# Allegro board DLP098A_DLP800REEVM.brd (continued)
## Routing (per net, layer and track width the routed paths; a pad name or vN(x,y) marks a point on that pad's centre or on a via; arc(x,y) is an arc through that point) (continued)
M_DDA14_N: length 124.5
  TOP w0.108: U8.B23 v1(46.2,42.39)
  03_SIG1 w0.108: v1(96.18,76.98) 95.67,77.49 95.67,78.79 95.28,79.18 87,79.18 86.53,78.71 86.53,66.09 84.75,64.31 80.52,64.31 79.94,63.73 79.94,56.14 76.47,52.68 60.59,52.68 59.9,53.37 58.27,53.37 57.99,53.65 57.99,53.96 58.35,54.32 60.51,54.32 61.46,53.37 74.97,53.37 75.32,53.73 75.32,54.24 74.98,54.58 61.94,54.58 60.16,56.37 58.1,56.37 56.15,54.42 56.15,49.62 55.61,49.08 55.61,46.45 51.05,41.88 46.31,41.88 46.2,41.99 v1(46.2,42.39)
  BOTTOM w0.108: J500.G34 v1(96.18,76.98)
M_DDA14_P: length 124.5
  TOP w0.108: U8.C23 v1(46.2,41.12)
  03_SIG1 w0.108: v1(46.2,41.12) 46.2,41.52 46.31,41.63 51.15,41.63 55.86,46.34 55.86,48.98 56.4,49.52 56.4,54.32 58.2,56.11 60.05,56.11 61.84,54.33 74.88,54.33 75.07,54.14 75.07,53.83 74.86,53.62 61.57,53.62 60.61,54.58 58.25,54.58 57.73,54.06 57.73,53.54 58.16,53.11 59.79,53.11 60.48,52.42 76.58,52.42 80.19,56.04 80.19,63.62 80.62,64.06 84.85,64.06 86.78,65.99 86.78,78.61 87.1,78.93 95.17,78.93 95.41,78.68 95.41,76.97 95.28,76.84 95.06,76.84 v1(94.91,76.98)
  BOTTOM w0.108: J500.G33 v1(94.91,76.98)
M_DDA15_N: length 124.5
  TOP w0.108: U8.K24 v1(47.47,32.23)
  03_SIG1 w0.108: v1(101.26,75.71) 101.2,75.71 100.83,76.08 100.44,76.47 99.53,76.47 99.23,76.17 99.23,73.87 101.4,71.71 104.02,71.71 105.2,70.53 105.2,68.79 106.77,67.22 112.11,67.22 115.08,64.25 115.08,58.08 112.02,55.02 87.74,55.02 82.81,50.08 82.81,46.6 70.52,34.31 60.25,34.31 58.84,35.72 58.84,37.99 58.46,38.37 57.86,38.37 57.41,37.92 57.41,31.96 55.71,30.26 48.54,30.26 48.24,30.56 48.24,31.47 47.98,31.72 47.58,31.72 47.47,31.83 v1(47.47,32.23)
  BOTTOM w0.108: J500.H38 v1(101.26,75.71)
M_DDA15_P: length 124.5
  TOP w0.108: U8.L24 v1(47.47,30.96)
  03_SIG1 w0.108: v1(99.99,75.71) 100.14,75.56 100.36,75.56 100.53,75.73 100.53,76.02 100.33,76.22 99.64,76.22 99.49,76.07 99.49,73.98 101.5,71.97 104.13,71.97 105.46,70.64 105.46,68.89 106.88,67.48 112.22,67.48 115.34,64.35 115.34,57.98 112.13,54.76 87.85,54.76 83.06,49.98 83.06,46.5 70.62,34.05 60.15,34.05 58.59,35.61 58.59,37.89 58.36,38.12 57.97,38.12 57.67,37.82 57.67,31.85 55.82,30 48.43,30 47.98,30.45 47.98,31.36 47.87,31.47 47.58,31.47 47.47,31.36 v1(47.47,30.96)
  BOTTOM w0.108: J500.H37 v1(99.99,75.71)
M_DDB00_N: length 124.5
  TOP w0.108: U8.Z18 v1(39.85,15.72)
  08_SIG3 w0.108: v1(39.85,15.72) 39.85,15.45 40,15.31 40.25,15.31 40.36,15.43 40.36,19.92 41.43,21 44.85,21 45.42,21.56 47.81,21.56 47.98,21.73 47.98,22.53 48.29,22.83 50.41,22.83 53.34,25.76 53.34,43.04 62.5,52.2 82.33,52.2 82.96,52.83 82.96,54.2 82.2,54.96 74.98,54.96 72.29,57.64 69.53,57.64 69.03,58.14 69.03,61.21 69.57,61.74 84.78,61.74 86.25,63.21 86.25,72.65 86.52,72.91 86.52,73.49 86.35,73.67 85.69,73.67 85.53,73.51 85.53,73.18 85.64,73.07 85.92,73.07 v1(86.02,73.17)
  BOTTOM w0.108: J500.K26 v1(86.02,73.17)
M_DDB00_P: length 124.5
  TOP w0.108: U8.Z19 v1(41.12,15.72)
  08_SIG3 w0.108: v1(41.12,15.72) 40.72,15.72 40.62,15.83 40.62,19.82 41.54,20.74 44.96,20.74 45.52,21.31 47.92,21.31 48.24,21.63 48.24,22.42 48.39,22.58 50.52,22.58 53.59,25.66 53.59,42.94 62.6,51.95 82.44,51.95 83.22,52.73 83.22,54.3 82.31,55.21 75.08,55.21 72.4,57.89 69.64,57.89 69.29,58.25 69.29,61.1 69.67,61.49 84.89,61.49 86.51,63.11 86.51,72.54 86.78,72.81 86.78,73.6 86.45,73.92 85.59,73.92 85.28,73.61 85.28,73.28 85.17,73.17 v1(84.75,73.17)
  BOTTOM w0.108: J500.K25 v1(84.75,73.17)
M_DDB01_N: length 124.5
  TOP w0.108: U8.T24 v1(47.47,23.34)
  08_SIG3 w0.108: v1(47.47,23.34) 47.47,22.94 47.37,22.83 47.21,22.83 46.97,23.08 46.97,24.88 47.21,25.12 50.54,25.12 52.82,27.39 52.82,43.48 62.45,53.11 81.98,53.11 82.24,53.38 82.24,54.01 81.96,54.3 66.39,54.3 66.23,54.46 66.23,54.79 66.4,54.96 71.57,54.96 72.07,55.46 72.07,56.47 71.63,56.9 68.46,56.9 68.01,57.35 68.01,61.94 68.49,62.42 84.32,62.42 85.34,63.44 85.34,71.53 84.24,72.63 84.24,74.04 84.12,74.16 84.12,74.32 84.24,74.44 v1(84.75,74.44)
  BOTTOM w0.108: J500.J25 v1(84.75,74.44)
M_DDB01_P: length 124.5
  TOP w0.108: U8.U24 v1(47.47,22.07)
  08_SIG3 w0.108: v1(47.47,22.07) 47.47,22.47 47.37,22.58 47.11,22.58 46.72,22.97 46.72,24.99 47.1,25.37 50.44,25.37 52.57,27.5 52.57,43.58 62.35,53.37 81.87,53.37 81.99,53.48 81.99,53.91 81.85,54.04 66.28,54.04 65.98,54.35 65.98,54.9 66.29,55.21 71.46,55.21 71.81,55.57 71.81,56.36 71.53,56.65 68.35,56.65 67.75,57.25 67.75,62.05 68.38,62.68 84.21,62.68 85.08,63.55 85.08,71.43 83.99,72.52 83.99,73.93 v1(83.48,74.44)
  BOTTOM w0.108: J500.J24 v1(83.48,74.44)
M_DDB02_N: length 124.5
  TOP w0.108: U8.N23 v1(46.2,27.15)
  08_SIG3 w0.108: v1(82.21,78.25) 81.91,78.25 81.8,78.36 81.8,78.84 81.43,79.22 77.24,79.22 76.37,78.35 76.37,73 77.31,72.06 82.38,72.06 83.16,71.29 83.16,64.27 82.51,63.62 68.23,63.62 67.95,63.9 67.95,64.3 68.22,64.57 81.11,64.57 81.41,64.86 81.41,65.5 81.14,65.76 67.65,65.76 66.63,64.75 66.63,56.86 66.01,56.24 63.98,56.24 51.79,44.04 51.79,29.39 50.31,27.91 46.98,27.91 46.7,27.63 46.7,26.88 46.47,26.64 46.31,26.64 46.2,26.75 v1(46.2,27.15)
  BOTTOM w0.108: J500.F23 v1(82.21,78.25)
M_DDB02_P: length 124.5
  TOP w0.108: U8.P23 v1(46.2,25.88)
  08_SIG3 w0.108: v1(46.2,25.88) 46.2,26.28 46.31,26.39 46.57,26.39 46.95,26.77 46.95,27.53 47.08,27.66 50.42,27.66 52.04,29.28 52.04,43.94 64.09,55.98 66.11,55.98 66.89,56.76 66.89,64.64 67.76,65.51 81.04,65.51 81.15,65.39 81.15,64.97 81.01,64.82 68.12,64.82 67.7,64.4 67.7,63.79 68.12,63.37 82.61,63.37 83.41,64.16 83.41,71.39 82.49,72.31 77.42,72.31 76.62,73.1 76.62,78.25 77.35,78.97 81.32,78.97 81.55,78.74 81.55,78.23 81.41,78.09 81.11,78.09 v1(80.94,78.25)
  BOTTOM w0.108: J500.F22 v1(80.94,78.25)
M_DDB03_N: length 124.4
  TOP w0.108: U8.Y18 v1(39.85,16.99)
  10_SIG4 w0.108: v1(39.85,16.99) 40.25,16.99 40.36,17.1 40.36,20.01 41.13,20.78 43.64,20.78 44.73,21.87 44.73,30.89 45.56,31.72 50.23,31.72 50.89,32.38 50.89,45.47 51.32,45.9 52.05,45.9 52.49,45.46 52.49,35.56 52.78,35.27 53.76,35.27 54.41,35.92 55.86,35.92 56.22,36.28 56.22,45.25 61.1,50.13 71.58,50.13 76.82,55.36 81.8,55.36 83.06,56.62 83.06,72.11 82.71,72.45 82.71,81.14 82.55,81.3 80.54,81.3 80.33,81.1 80.33,80.62 80.45,80.5 80.76,80.5 80.94,80.68 v1(80.94,80.79)
  BOTTOM w0.108: J500.E22 v1(80.94,80.79)
M_DDB03_P: length 124.4
  TOP w0.108: U8.Y19 v1(41.12,16.99)
  10_SIG4 w0.108: v1(41.12,16.99) 40.72,16.99 40.62,17.1 40.62,19.91 41.24,20.53 43.75,20.53 44.99,21.77 44.99,30.79 45.67,31.47 50.33,31.47 51.14,32.28 51.14,45.36 51.43,45.65 51.95,45.65 52.24,45.36 52.24,35.45 52.68,35.02 53.87,35.02 54.51,35.66 55.97,35.66 56.48,36.17 56.48,45.15 61.2,49.87 71.69,49.87 76.92,55.11 81.91,55.11 83.31,56.51 83.31,72.21 82.97,72.56 82.97,81.24 82.66,81.55 80.43,81.55 v1(79.67,80.79)
  BOTTOM w0.108: J500.E21 v1(79.67,80.79)
M_DDB04_N: length 124.5
  TOP w0.108: U8.AA19 v1(41.12,14.45)
  08_SIG3 w0.108: v1(86.02,78.25) 86.02,78.03 85.89,77.89 85.54,77.89 85.4,78.03 85.4,78.81 85.57,78.98 88.7,78.98 89.06,78.62 89.06,72.22 88.46,71.62 88.46,61.55 86.64,59.74 78.21,59.74 77.44,58.96 77.44,57.61 78.24,56.8 84.31,56.8 85.57,55.54 85.57,51.39 84.6,50.42 63.23,50.42 55.12,42.31 55.12,24.84 50.58,20.29 41.98,20.29 41.63,19.95 41.63,14.56 41.52,14.45 v1(41.12,14.45)
  BOTTOM w0.108: J500.F26 v1(86.02,78.25)
M_DDB04_P: length 124.5
  TOP w0.108: U8.AA20 v1(42.39,14.45)
  08_SIG3 w0.108: v1(84.75,78.25) 85.04,78.25 85.15,78.36 85.15,78.92 85.47,79.24 88.8,79.24 89.32,78.72 89.32,72.12 88.71,71.51 88.71,61.45 86.74,59.48 78.32,59.48 77.69,58.86 77.69,57.71 78.35,57.06 84.41,57.06 85.82,55.64 85.82,51.29 84.71,50.17 63.34,50.17 55.37,42.21 55.37,24.73 50.68,20.04 42.08,20.04 41.89,19.85 41.89,14.56 41.99,14.45 v1(42.39,14.45)
  BOTTOM w0.108: J500.F25 v1(84.75,78.25)
M_DDB05_N: length 124.5
  TOP w0.108: U8.W24 v1(47.47,19.53)
  10_SIG4 w0.108: v1(47.47,19.53) 47.47,19.13 47.37,19.02 45.88,19.02 45.7,19.2 45.7,29.39 46.34,30.03 50.37,30.03 54.95,34.62 57.81,34.62 58.61,35.42 58.61,36.52 57.53,37.61 57.53,44.87 61.53,48.88 72.09,48.88 77.38,54.16 91.07,54.16 91.85,54.94 97.38,54.94 97.87,54.46 98.87,54.46 99.21,54.8 99.21,55.46 98.88,55.79 98.51,55.79 97.14,57.17 87.41,57.17 85.67,58.91 85.67,71.15 84.24,72.58 84.24,78.87 84.14,78.98 84.14,80.7 84.26,80.83 84.71,80.83 v1(84.75,80.79)
  BOTTOM w0.108: J500.E25 v1(84.75,80.79)
M_DDB05_P: length 124.5
  TOP w0.108: U8.X24 v1(47.47,18.26)
  10_SIG4 w0.108: v1(83.48,80.79) 83.88,80.39 83.88,78.88 83.99,78.77 83.99,72.47 85.42,71.05 85.42,58.8 87.3,56.91 97.03,56.91 98.41,55.54 98.78,55.54 98.96,55.36 98.96,54.91 98.76,54.71 97.98,54.71 97.49,55.2 91.75,55.2 90.97,54.41 77.27,54.41 71.99,49.13 61.43,49.13 57.27,44.97 57.27,37.5 58.35,36.42 58.35,35.53 57.7,34.87 54.85,34.87 50.26,30.29 46.24,30.29 45.45,29.49 45.45,19.1 45.77,18.77 47.37,18.77 47.47,18.66 v1(47.47,18.26)
  BOTTOM w0.108: J500.E24 v1(83.48,80.79)
M_DDB06_N: length 124.5
  TOP w0.108: U8.P25 v1(48.74,25.88)
  10_SIG4 w0.108: v1(48.74,25.88) 48.74,25.48 48.85,25.37 49.01,25.37 49.24,25.61 49.24,26.24 49.64,26.64 50.42,26.64 50.82,27.04 50.82,27.62 56.03,32.83 56.56,32.83 57.02,32.38 57.02,31.98 51.95,26.92 51.95,26.55 52.14,26.36 52.42,26.36 60.77,34.71 60.77,37.08 59.45,38.39 59.45,44.35 62.27,47.17 73.04,47.17 77.77,51.9 92.63,51.9 94.09,53.36 96.57,53.36 97.08,52.85 100.03,52.85 100.91,53.72 100.91,56.71 100.18,57.44 99.17,57.44 97.78,58.82 89.13,58.82 87.45,60.51 87.45,71.41 87.8,71.76 87.8,73.61 88.13,73.93 89.07,73.93 v1(89.83,73.17)
  BOTTOM w0.108: J500.K29 v1(89.83,73.17)
M_DDB06_P: length 124.5
  TOP w0.108: U8.R25 v1(48.74,24.61)
  10_SIG4 w0.108: v1(48.74,24.61) 48.74,25.01 48.85,25.12 49.11,25.12 49.5,25.51 49.5,26.14 49.75,26.39 50.52,26.39 51.07,26.94 51.07,27.51 56.14,32.58 56.45,32.58 56.76,32.27 56.76,32.09 51.69,27.02 51.69,26.45 52.03,26.11 52.52,26.11 61.02,34.61 61.02,37.18 59.71,38.5 59.71,44.24 62.38,46.92 73.15,46.92 77.88,51.65 92.74,51.65 94.2,53.11 96.47,53.11 96.98,52.6 100.14,52.6 101.16,53.62 101.16,56.81 100.28,57.69 99.27,57.69 97.89,59.08 89.24,59.08 87.7,60.61 87.7,71.31 88.06,71.66 88.06,73.5 88.24,73.68 88.96,73.68 89.15,73.5 89.15,73.22 89.04,73.11 88.62,73.11 v1(88.56,73.17)
  BOTTOM w0.108: J500.K28 v1(88.56,73.17)
M_DDB07_N: length 124.5
  TOP w0.108: U8.Y26 v1(50.01,16.99)
  10_SIG4 w0.108: v1(88.56,74.44) 87.8,75.2 85.69,75.2 85.26,74.77 85.26,72.77 86.41,71.62 86.41,59.62 88.23,57.8 97.45,57.8 98.72,56.53 99.54,56.53 99.88,56.18 99.88,54.38 99.28,53.78 97.64,53.78 97.12,54.3 93.43,54.3 92.08,52.95 91.17,52.95 90.74,53.39 77.78,53.39 72.57,48.18 61.86,48.18 58.49,44.81 58.49,37.78 59.77,36.5 59.77,35.04 58.6,33.88 55.31,33.88 50.87,29.43 47.32,29.43 46.71,28.82 46.71,20.43 47.1,20.04 49,20.04 49.26,19.78 49.26,17.89 49.65,17.5 49.91,17.5 50.01,17.39 v1(50.01,16.99)
  BOTTOM w0.108: J500.J28 v1(88.56,74.44)
M_DDB07_P: length 124.5
  TOP w0.108: U8.X26 v1(50.01,18.26)
  10_SIG4 w0.108: v1(50.01,18.26) 50.01,17.86 49.91,17.75 49.75,17.75 49.51,18 49.51,19.89 49.1,20.29 47.21,20.29 46.96,20.54 46.96,28.72 47.42,29.17 50.97,29.17 55.42,33.62 58.71,33.62 60.03,34.94 60.03,36.61 58.75,37.89 58.75,44.7 61.97,47.92 72.67,47.92 77.89,53.14 90.63,53.14 91.07,52.7 92.19,52.7 93.53,54.05 97.02,54.05 97.54,53.52 99.38,53.52 100.14,54.28 100.14,56.28 99.64,56.78 98.82,56.78 97.55,58.05 88.33,58.05 86.66,59.72 86.66,71.73 85.51,72.88 85.51,74.67 85.79,74.95 87.69,74.95 87.98,74.67 87.98,74.21 87.74,73.97 87.45,73.97 87.29,74.13 v1(87.29,74.44)
  BOTTOM w0.108: J500.J27 v1(87.29,74.44)
M_DDB08_N: length 124.5
  TOP w0.108: U8.Y21 v1(43.66,16.99)
  10_SIG4 w0.108: v1(43.66,16.99) 43.66,16.59 43.77,16.48 44.17,16.48 44.42,16.23 44.42,15.44 44.65,15.21 51.87,15.21 82.5,45.85 94.68,45.85 95.93,47.1 103.07,47.1 106.58,50.61 106.58,63.43 100.54,69.46 100.54,71.43 99.23,72.74 99.23,78.8 98.46,79.57 90.24,79.57 89.18,78.51 89.18,77.92 89.29,77.81 89.72,77.81 89.83,77.92 v1(89.83,78.25)
  BOTTOM w0.108: J500.F29 v1(89.83,78.25)
M_DDB08_P: length 124.5
  TOP w0.108: U8.Z21 v1(43.66,15.72)
  10_SIG4 w0.108: v1(88.56,78.25) 90.13,79.82 98.56,79.82 99.48,78.9 99.48,72.84 100.79,71.53 100.79,69.57 106.83,63.53 106.83,50.5 103.18,46.85 96.04,46.85 94.78,45.6 82.61,45.6 51.97,14.96 44.54,14.96 44.17,15.33 44.17,16.12 44.06,16.23 43.77,16.23 43.66,16.12 v1(43.66,15.72)
  BOTTOM w0.108: J500.F28 v1(88.56,78.25)
M_DDB09_N: length 124.5
  TOP w0.108: U8.U25 v1(48.74,22.07)
  08_SIG3 w0.108: v1(88.56,80.79) 88.25,80.79 88.14,80.9 88.14,81.26 87.84,81.56 84.33,81.56 83.99,81.22 83.99,76.62 84.39,76.22 87.68,76.22 87.79,76.1 87.79,72.85 87.23,72.28 87.23,62.27 85.65,60.69 71.63,60.69 71.24,60.3 71.24,59.13 71.59,58.78 72.9,58.78 75.76,55.92 83.49,55.92 84.47,54.95 84.47,52 83.77,51.3 62.86,51.3 54.21,42.65 54.21,25.3 50.47,21.56 48.85,21.56 48.74,21.67 v1(48.74,22.07)
  BOTTOM w0.108: J500.E28 v1(88.56,80.79)
M_DDB09_P: length 124.5
  TOP w0.108: U8.V25 v1(48.74,20.8)
  08_SIG3 w0.108: v1(48.74,20.8) 48.74,21.2 48.85,21.31 50.58,21.31 54.47,25.2 54.47,42.54 62.97,51.04 83.87,51.04 84.72,51.89 84.72,55.05 83.59,56.18 75.87,56.18 73.01,59.03 71.69,59.03 71.5,59.23 71.5,60.19 71.74,60.43 85.76,60.43 87.48,62.16 87.48,72.18 88.05,72.74 88.05,76.2 87.78,76.47 84.5,76.47 84.24,76.73 84.24,81.11 84.43,81.3 87.74,81.3 87.89,81.15 87.89,80.74 87.77,80.62 87.46,80.62 v1(87.29,80.79)
  BOTTOM w0.108: J500.E27 v1(87.29,80.79)
M_DDB10_N: length 124.5
  TOP w0.108: U8.AA24 v1(47.47,14.45)
  08_SIG3 w0.108: v1(47.47,14.45) 47.47,14.85 47.58,14.96 50.66,14.96 58.03,22.33 58.03,40.86 63.67,46.49 69.17,46.49 70.17,45.5 79.07,45.5 80.95,47.38 98.11,47.38 98.96,48.23 98.96,50.51 97.97,51.5 89.58,51.5 88.88,52.19 88.88,56.09 89.23,56.44 95.86,56.44 96.99,57.58 96.99,61.66 95.9,62.76 93.5,62.76 93.16,63.09 93.16,68 92.36,68.8 92.36,70.77 93.23,71.64 93.23,73.06 93.34,73.17 v1(93.64,73.17)
  BOTTOM w0.108: J500.K32 v1(93.64,73.17)
M_DDB10_P: length 124.5
  TOP w0.108: U8.Z24 v1(47.47,15.72)
  08_SIG3 w0.108: v1(47.47,15.72) 47.47,15.32 47.58,15.21 50.56,15.21 57.78,22.44 57.78,40.96 63.56,46.75 69.28,46.75 70.28,45.75 78.96,45.75 80.84,47.63 98,47.63 98.71,48.33 98.71,50.4 97.87,51.24 89.47,51.24 88.63,52.09 88.63,56.2 89.13,56.7 95.75,56.7 96.74,57.68 96.74,61.56 95.79,62.5 93.39,62.5 92.91,62.99 92.91,67.89 92.1,68.7 92.1,70.88 92.97,71.75 92.97,73.22 92.87,73.33 92.53,73.33 v1(92.37,73.17)
  BOTTOM w0.108: J500.K31 v1(92.37,73.17)
M_DDB11_N: length 124.5
  TOP w0.108: U8.R26 v1(50.01,24.61)
  10_SIG4 w0.108: v1(50.01,24.61) 50.01,25.01 50.12,25.12 50.68,25.12 51.22,24.58 52.36,24.58 60.84,33.07 61.05,33.07 61.34,32.77 61.34,32.57 57.43,28.65 57.43,28.13 57.88,27.68 58.37,27.68 62.94,32.24 62.94,36.83 60.72,39.05 60.72,43.73 62.86,45.87 75.4,45.87 79.82,50.29 92.71,50.29 93.66,51.25 100.9,51.25 102.34,52.69 102.34,57.82 101.36,58.8 99.81,58.8 98.38,60.23 89.99,60.23 88.74,61.48 88.74,70.94 89.98,72.17 91.23,72.17 91.86,72.81 91.86,73.93 v1(92.37,74.44)
  BOTTOM w0.108: J500.J31 v1(92.37,74.44)
M_DDB11_P: length 124.5
  TOP w0.108: U8.P26 v1(50.01,25.88)
  10_SIG4 w0.108: v1(91.1,74.44) 91.13,74.47 91.61,74.47 91.72,74.36 91.72,74.15 91.61,74.04 91.61,72.91 91.12,72.43 89.87,72.43 88.49,71.05 88.49,61.37 89.88,59.98 98.27,59.98 99.7,58.54 101.26,58.54 102.09,57.71 102.09,52.8 100.79,51.5 93.56,51.5 92.6,50.55 79.72,50.55 75.3,46.13 62.76,46.13 60.46,43.83 60.46,38.94 62.68,36.72 62.68,32.35 58.27,27.93 57.99,27.93 57.68,28.24 57.68,28.55 61.6,32.46 61.6,32.88 61.15,33.32 60.74,33.32 52.25,24.84 51.32,24.84 50.78,25.37 50.12,25.37 50.01,25.48 v1(50.01,25.88)
  BOTTOM w0.108: J500.J30 v1(91.1,74.44)
M_DDB12_N: length 124.5
  TOP w0.108: v1(48.74,18.26) U8.X25
  10_SIG4 w0.108: v1(93.64,78.25) 93.39,78 93.39,77.85 93.5,77.74 95.18,77.74 95.42,77.99 95.42,78.59 95.88,79.05 97.83,79.05 98.21,78.66 98.21,72.33 99.09,71.45 99.09,67.16 105.78,60.47 105.78,50.96 102.61,47.79 95.28,47.79 94.2,46.71 82.32,46.71 52.99,17.38 52.31,17.38 51.88,17.81 51.88,20.1 51.73,20.25 51.26,20.25 51.09,20.08 51.09,16.64 50.68,16.23 45.71,16.23 45.44,16.49 45.44,17.44 45.75,17.75 48.63,17.75 48.74,17.86 v1(48.74,18.26)
  BOTTOM w0.108: J500.F32 v1(93.64,78.25)
M_DDB12_P: length 124.5
  TOP w0.108: U8.Y25 v1(48.74,16.99)
  10_SIG4 w0.108: v1(48.74,16.99) 48.74,17.39 48.64,17.5 45.86,17.5 45.7,17.34 45.7,16.6 45.81,16.48 50.57,16.48 50.83,16.74 50.83,20.18 51.16,20.51 51.84,20.51 52.14,20.21 52.14,17.92 52.42,17.63 52.88,17.63 82.21,46.96 94.09,46.96 95.18,48.04 102.51,48.04 105.53,51.06 105.53,60.36 98.84,67.05 98.84,71.35 97.96,72.22 97.96,78.56 97.72,78.79 95.99,78.79 95.67,78.48 95.67,77.88 95.28,77.49 93.39,77.49 93.14,77.74 93.14,78.5 92.98,78.66 92.57,78.66 92.37,78.46 v1(92.37,78.25)
  BOTTOM w0.108: J500.F31 v1(92.37,78.25)
M_DDB13_N: length 124.5
  TOP w0.108: U8.W23 v1(46.2,19.53)
  08_SIG3 w0.108: v1(92.37,80.79) 92.04,80.79 91.93,80.9 91.93,81.26 91.65,81.55 90.72,81.55 90.34,81.17 90.34,71.61 89.46,70.74 89.46,61.1 90.19,60.37 93.21,60.37 93.53,60.05 93.53,59.21 93.17,58.85 78.97,58.85 78.63,58.51 78.63,58.02 78.97,57.68 85.18,57.68 86.56,56.3 86.56,50.59 85.5,49.53 63.62,49.53 55.99,41.9 55.99,24.29 50.72,19.02 46.31,19.02 46.2,19.13 v1(46.2,19.53)
  BOTTOM w0.108: J500.E31 v1(92.37,80.79)
M_DDB13_P: length 124.5
  TOP w0.108: U8.X23 v1(46.2,18.26)
  08_SIG3 w0.108: v1(46.2,18.26) 46.2,18.66 46.31,18.77 50.83,18.77 56.24,24.19 56.24,41.8 63.72,49.28 85.61,49.28 86.82,50.49 86.82,56.41 85.29,57.94 79.07,57.94 78.89,58.12 78.89,58.4 79.08,58.59 93.27,58.59 93.78,59.11 93.78,60.16 93.31,60.63 90.3,60.63 89.72,61.2 89.72,70.63 90.59,71.51 90.59,81.07 90.82,81.3 91.54,81.3 91.68,81.16 91.68,80.71 91.56,80.59 91.31,80.59 v1(91.1,80.79)
  BOTTOM w0.108: J500.E30 v1(91.1,80.79)
M_DDB14_N: length 124.4
  TOP w0.108: U8.Z23 v1(46.2,15.72)
  08_SIG3 w0.108: v1(97.45,73.17) 97.12,73.17 97,73.05 97,71.86 96.53,71.39 94.65,71.39 94.15,71.89 94.15,73.45 93.92,73.68 92.06,73.68 91.86,73.48 91.86,72.4 91.47,72.01 91.47,62.26 92.06,61.66 95.12,61.66 96.09,60.69 96.09,58.35 95.07,57.33 88.45,57.33 87.83,56.71 87.83,50.84 88.37,50.3 92.89,50.3 93.4,49.79 93.4,48.78 92.89,48.28 78.78,48.28 76.96,46.46 70.57,46.46 69.52,47.5 63.19,47.5 57.15,41.46 57.15,22.91 50.47,16.23 46.31,16.23 46.2,16.12 v1(46.2,15.72)
  BOTTOM w0.108: J500.K35 v1(97.45,73.17)
M_DDB14_P: length 124.4
  TOP w0.108: U8.Y23 v1(46.2,16.99)
  08_SIG3 w0.108: v1(96.18,73.17) 96.39,73.38 96.64,73.38 96.74,73.28 96.74,71.96 96.42,71.64 94.76,71.64 94.4,71.99 94.4,73.56 94.03,73.93 91.95,73.93 91.61,73.59 91.61,72.51 91.21,72.11 91.21,62.15 91.96,61.4 95.02,61.4 95.83,60.59 95.83,58.45 94.96,57.58 88.34,57.58 87.57,56.82 87.57,50.74 88.27,50.04 92.79,50.04 93.14,49.69 93.14,48.89 92.79,48.53 78.68,48.53 76.86,46.71 70.67,46.71 69.63,47.76 63.08,47.76 56.9,41.57 56.9,23.02 50.36,16.48 46.31,16.48 46.2,16.59 v1(46.2,16.99)
  BOTTOM w0.108: J500.K34 v1(96.18,73.17)
M_DDB15_N: length 124.5
  TOP w0.108: U8.P24 v1(47.47,25.88)
  10_SIG4 w0.108: v1(96.18,74.44) 95.67,73.93 95.67,72.68 95.06,72.06 93.08,72.06 92.25,71.23 90.32,71.23 89.78,70.7 89.78,62.86 91.38,61.26 99.29,61.26 100.71,59.85 102.04,59.85 103.65,58.24 103.65,52.29 101.37,50.01 94.49,50.01 93.59,49.12 80.01,49.12 78.04,47.14 78.04,45.96 54.27,22.19 53.68,22.19 53.34,22.53 53.34,23.03 57.22,26.91 57.22,27.07 56.95,27.34 56.64,27.34 52.22,22.91 51.31,22.91 50.37,23.85 48.39,23.85 47.99,24.25 47.99,26.14 47.74,26.39 47.58,26.39 47.47,26.28 v1(47.47,25.88)
  BOTTOM w0.108: J500.J34 v1(96.18,74.44)
M_DDB15_P: length 124.5
  TOP w0.108: U8.N24 v1(47.47,27.15)
  10_SIG4 w0.108: v1(94.91,74.44) 94.97,74.5 95.37,74.5 95.5,74.38 95.5,74.12 95.42,74.04 95.42,72.78 94.95,72.32 92.97,72.32 92.14,71.49 90.21,71.49 89.53,70.8 89.53,62.76 91.28,61.01 99.19,61.01 100.6,59.59 101.93,59.59 103.39,58.13 103.39,52.4 101.26,50.27 94.38,50.27 93.49,49.37 79.9,49.37 77.78,47.25 77.78,46.06 54.16,22.44 53.78,22.44 53.59,22.63 53.59,22.93 57.47,26.8 57.47,27.17 57.05,27.59 56.53,27.59 52.11,23.17 51.42,23.17 50.48,24.11 48.49,24.11 48.24,24.36 48.24,26.25 47.84,26.64 47.58,26.64 47.47,26.75 v1(47.47,27.15)
  BOTTOM w0.108: J500.J33 v1(94.91,74.44)
M_SCTRLA_N: length 124.4
  TOP w0.108: U8.F26 v1(50.01,37.31)
  05_SIG2 w0.108: v1(99.99,76.98) 99.99,76.66 99.88,76.56 99.6,76.56 99.48,76.68 99.48,77.24 99.72,77.49 100.19,77.49 100.5,77.18 100.5,72.77 98.91,71.18 98.91,67.78 93.6,62.47 85.67,62.47 69.1,45.89 63.65,45.89 60.91,43.15 60.91,38.85 63.84,35.92 71.77,35.92 73.68,34.01 73.68,26.68 71.71,24.7 54.34,24.7 51.05,27.99 51.05,36.25 50.49,36.8 49.85,36.8 49.75,36.91 49.75,37.2 49.85,37.31 v1(50.01,37.31)
  BOTTOM w0.108: J500.G37 v1(99.99,76.98)
M_SCTRLA_P: length 124.5
  TOP w0.108: U8.G26 v1(50.01,36.04)
  05_SIG2 w0.108: v1(98.72,76.98) 99.12,76.98 99.23,77.09 99.23,77.35 99.62,77.74 100.29,77.74 100.75,77.28 100.75,72.66 99.17,71.08 99.17,67.68 93.7,62.21 85.78,62.21 69.2,45.64 63.75,45.64 61.16,43.05 61.16,38.96 63.95,36.17 71.87,36.17 73.93,34.11 73.93,26.57 71.81,24.45 54.23,24.45 50.79,27.89 50.79,36.14 50.38,36.55 50.12,36.55 50.01,36.44 v1(50.01,36.04)
  BOTTOM w0.108: J500.G36 v1(98.72,76.98)
M_SCTRLB_N: length 124.4
  TOP w0.108: U8.V26 v1(50.01,20.8)
  10_SIG4 w0.108: v1(97.45,78.25) 96.94,77.74 96.94,72.19 95.23,70.48 93.33,70.48 91.51,68.66 91.51,66.21 91.83,65.89 98.83,65.89 99.29,65.43 99.29,63.7 98.75,63.16 92.49,63.16 92.32,62.99 92.32,62.44 92.47,62.3 99.84,62.3 101.22,60.92 103.4,60.92 104.77,59.55 104.77,51.51 102.07,48.82 94.78,48.82 93.87,47.9 81.81,47.9 55.21,21.31 50.12,21.31 50.01,21.2 v1(50.01,20.8)
  BOTTOM w0.108: J500.F35 v1(97.45,78.25)
M_SCTRLB_P: length 124.4
  TOP w0.108: U8.U26 v1(50.01,22.07)
  10_SIG4 w0.108: v1(96.18,78.25) 96.26,78.33 96.61,78.33 96.76,78.19 96.76,77.92 96.69,77.85 96.69,72.3 95.12,70.73 93.22,70.73 91.26,68.77 91.26,66.1 91.73,65.63 98.72,65.63 99.03,65.32 99.03,63.81 98.65,63.42 92.39,63.42 92.07,63.1 92.07,62.34 92.36,62.04 99.74,62.04 101.12,60.66 103.3,60.66 104.51,59.45 104.51,51.62 101.97,49.07 94.67,49.07 93.76,48.16 81.7,48.16 55.11,21.56 50.12,21.56 50.01,21.67 v1(50.01,22.07)
  BOTTOM w0.108: J500.F34 v1(96.18,78.25)
MBRST0: length 70
  TOP w0.191: U7.22 91.65,35.91 92.18,36.43 92.18,38.59 TP23.1 ; U8.E14 v1(34.77,38.58)
  BOTTOM w0.191: v1(34.77,38.58) 34.82,38.58 35.45,39.22 52.14,39.22 56.74,34.62 70.89,34.62 76.02,39.76 81.12,39.76 82.5,41.13 86.5,41.13 87.55,40.08 90.86,40.08 91.33,39.61 TP23.1
MBRST1: length 74.9
  TOP w0.191: TP22.1 91.29,41.64 91.29,38.46 90.7,37.87 90.7,35.73 90.66,35.69 U7.24 ; U8.D13 v1(32.23,39.85)
  BOTTOM w0.191: v1(32.23,39.85) 32.72,40.33 32.72,41.48 36.62,45.39 71.1,45.39 71.74,44.74 84.13,44.74 88.1,40.77 90.43,40.77 TP22.1
MBRST2: length 68.5
  TOP w0.191: U7.27 89.15,36.07 89.39,36.3 89.39,38.84 TP21.1 ; U8.E13 v1(32.23,38.58)
  BOTTOM w0.191: TP21.1 89.2,38.66 86.25,38.66 85.39,39.52 83.07,39.52 80.77,37.22 76.34,37.22 72.11,32.99 54.81,32.99 51.13,36.68 45.04,36.68 44.35,37.37 33.44,37.37 v1(32.23,38.58)
MBRST3: length 69.8
  TOP w0.191: U8.C12 v1(30.96,41.12) ; TP20.1 87.73,41.13 87.73,36.43 88.15,36.01 U7.29
  BOTTOM w0.191: TP20.1 84.76,45.38 72.25,45.38 71.61,46.02 34.94,46.02 31.6,42.68 31.6,41.76 v1(30.96,41.12)
MBRST4: length 66.7
  TOP w0.191: TP19.1 86.66,39.67 U7.32 ; U8.E12 v1(30.96,38.58)
  BOTTOM w0.191: v1(30.96,38.58) 31.6,39.22 33.09,39.22 34.36,37.95 51.96,37.95 56.28,33.62 70.99,33.62 75.32,37.96 80.42,37.96 82.6,40.14 86.18,40.14 TP19.1
MBRST5: length 67.8
  TOP w0.191: U8.C11 v1(29.69,41.12) ; TP18.1 85.07,37.04 85.08,37.03 85.08,36.67 85.65,36.1 U7.34
  BOTTOM w0.191: v1(29.69,41.12) U8.C11 30.33,37.92 31.26,36.98 43.81,36.98 45.39,35.41 51.44,35.41 54.71,32.13 72.27,32.13 76.63,36.49 81.08,36.49 83.06,38.46 TP18.1
MBRST6: length 65.6
  TOP w0.191: U8.D16 v1(37.31,39.85) ; U7.37 84.15,36.33 83.92,36.56 83.92,37.07 82.76,38.24 TP17.1
  BOTTOM w0.191: TP17.1 75.38,43.61 68.28,36.5 62.82,36.5 57.56,41.76 35.71,41.76 35.41,41.45 35.41,40.71 35.63,40.49 36.31,40.49 36.95,39.85 v1(37.31,39.85)
MBRST7: length 57.2
  TOP w0.191: U8.C15 v1(36.04,41.12) ; U7.39 83.15,35.06 83.15,36.69 82.65,37.19 82.07,37.19 81.89,37.37 81.89,39.48 TP16.1
  BOTTOM w0.191: v1(36.04,41.12) 36.4,41.12 37.03,40.49 56.29,40.49 61.22,35.56 70.03,35.56 75.47,41 TP16.1
MBRST8: length 58.1
  TOP w0.191: U7.62 83.16,20.53 82.9,20.27 82.9,18.63 82.17,17.91 82.17,15.93 81.46,15.21 79.35,15.21 78.79,15.77 78.79,16.33 TP15.1 ; U8.W14 v1(34.77,19.53)
  03_SIG1 w0.133: v1(34.77,19.53) 35.15,19.53 35.76,18.92 50.84,18.92 54.28,15.48 76.47,15.48 TP15.1
MBRST9: length 66.4
  TOP w0.191: U8.X13 v1(32.23,18.26) ; TP14.1 83.06,13.22 83.06,17.68 84.42,19.04 84.42,20.37 84.15,20.64 U7.64
  03_SIG1 w0.133: v1(32.23,18.26) 32.87,17.63 32.87,15.47 36.95,11.38 66.93,11.38 67.78,10.52 TP14.1
MBRST10: length 68.3
  TOP w0.191: U7.67 85.65,18.47 84.46,17.27 84.46,15.71 84.94,15.22 TP13.1 ; U8.W13 v1(32.23,19.53)
  03_SIG1 w0.133: TP13.1 84.53,12.96 44.29,12.96 43.46,13.79 36.87,13.79 35.36,15.3 35.36,18.71 35.16,18.91 34.1,18.91 33.64,19.37 32.4,19.37 v1(32.23,19.53)
MBRST11: length 74.3
  TOP w0.191: TP11.1 86.66,13.64 U7.69 ; U8.Y12 v1(30.96,16.99)
  03_SIG1 w0.133: v1(30.96,16.99) 31.65,16.31 31.65,15.24 36.21,10.68 66.36,10.68 68.18,8.86 85.57,8.86 TP11.1
MBRST12: length 71.8
  TOP w0.191: U7.72 88.15,20.5 88.05,20.4 88.05,19.48 88.37,19.16 TP10.1 ; U8.W12 v1(30.96,19.53)
  03_SIG1 w0.133: v1(30.96,19.53) 31.6,18.9 33.16,18.9 34.23,17.83 34.23,15.24 36.32,13.15 43.08,13.15 43.9,12.33 67.64,12.33 68.13,11.84 83.59,11.84 84.07,11.36 85.15,11.36 88.37,14.58 TP10.1
MBRST13: length 77.8
  TOP w0.191: U7.74 89.15,20.66 89.51,20.3 89.51,17.22 90.53,16.2 TP9.1 ; U8.Y11 v1(29.69,16.99)
  03_SIG1 w0.133: v1(29.69,16.99) 30.25,16.43 30.25,15.33 35.47,10.11 65.52,10.11 67.69,7.95 86.05,7.95 90.53,12.43 TP9.1
MBRST14: length 63.1
  TOP w0.191: U7.77 90.66,20.3 91.01,19.95 TP8.1 ; U8.Y15 v1(36.04,16.99)
  03_SIG1 w0.133: v1(36.04,16.99) 36.62,16.42 36.62,15.49 37.01,15.1 49.34,15.1 50.62,13.83 86.14,13.83 89.22,16.9 89.75,16.9 TP8.1
MBRST15: length 67.3
  TOP w0.191: U8.X16 v1(37.31,18.26) ; U7.79 91.65,19.18 92.94,17.89 TP7.1
  03_SIG1 w0.133: v1(37.31,18.26) 37.96,17.62 37.96,16.75 38.39,16.32 50.72,16.32 52.42,14.62 84.92,14.62 89.45,19.15 92.18,19.15 92.94,18.39 TP7.1
MODEB: length 74.2
  BOTTOM w0.191: J500.B12 66.97,84.6 66.97,85.91 66.37,86.51 50.41,86.51 49.5,85.6 49.5,69.38 48.2,68.08 22.92,68.08 TP1.1
Net_63: length 0.9
  TOP w0.191: 17.63,35.41 v1(16.99,36.04)
Net_64: length 0.9
  TOP w0.191: 17.63,34.14 v1(16.99,34.77)
Net_65: length 0.9
  TOP w0.191: 17.63,32.87 v1(16.99,33.5)
Net_66: length 0.9
  TOP w0.191: 20.17,32.87 v1(19.53,33.5)
Net_67: length 0.9
  TOP w0.191: 21.44,32.87 v1(20.8,33.5)
Net_68: length 0.9
  TOP w0.191: 20.17,31.6 v1(19.53,32.23)
Net_69: length 0.9
  TOP w0.191: 20.17,26.52 v1(19.53,25.88)
Net_70: length 0.9
  TOP w0.191: 17.63,25.25 v1(16.99,24.61)
Net_71: length 0.9
  TOP w0.191: 20.17,25.25 v1(19.53,24.61)
Net_72: length 0.9
  TOP w0.191: 21.44,25.25 v1(20.8,24.61)
Net_73: length 0.9
  TOP w0.191: 17.63,23.98 v1(16.99,23.34)
Net_74: length 0.9
  TOP w0.191: 17.63,22.71 v1(16.99,22.07)
Net_75: length 0.9
  TOP w0.191: 20.17,21.44 v1(19.53,20.8)
P3P3V1: length 5.2
  TOP w0.254: 104.98,68 104.99,68.01 C2.2 ; 106.86,68.22 106.35,68.22 L1.2 106.28,67.45 106.29,67.44
  TOP w0.508: 105.72,68.15 L1.2 106.28,68.84 ; 104.56,68.47 C2.2 ; C2.2 105.42,68.47 ; C2.2 104.99,68.9
  BOTTOM w0.508: J500.C39 v1(102.53,83.33)
P3P3V2: length 4
  BOTTOM w0.508: C6.2 93.53,68.47 ; C6.2 93.1,68.9 ; C6.2 92.67,68.47 ; 93.84,68.15 L3.2 ; L3.2 94.96,68.15 ; L3.2 94.4,68.84 ; J500.D36 v1(98.72,82.06)
  vias: v1(93.09,69.43) v1(94.41,69.43)
P3P3V3: length 4
  BOTTOM w0.508: C3.2 97.5,68.47 ; C3.2 97.06,68.9 ; C3.2 96.63,68.47 ; L2.2 98.36,68.84 ; L2.2 97.8,68.15 ; L2.2 98.92,68.15 ; J500.D38 v1(101.26,82.06)
  vias: v1(97.05,69.43) v1(98.2,69.44)
P3P3V4: length 5.2
  TOP w0.254: 101.02,68.01 101.03,68.01 C7.2
  TOP w0.381: 102.91,68.16 102.91,68.15 L4.2 102.32,67.48 102.33,67.47
  TOP w0.508: C7.2 101.46,68.47 ; C7.2 100.59,68.47 ; C7.2 101.03,68.9 ; 101.76,68.15 L4.2 102.32,68.84
  BOTTOM w0.508: J500.D40 v1(103.8,82.06)
RES0: length 0.9
  BOTTOM w0.191: J500.B40 v1(103.8,84.6)
RES1: length 0.9
  BOTTOM w0.191: J500.B01 v1(53,84.6)
S_DCLKA_N: length 124.5
  TOP w0.191: U8.B3 v1(19.53,42.39)
  05_SIG2 w0.108: v1(58.08,75.71) 57.32,76.48 52.48,76.48 52.37,76.58 52.37,77.36 52.5,77.49 59.77,77.49 60.11,77.83 60.11,78.88 59.77,79.23 53.34,79.23 53.23,79.34 53.23,79.61 53.43,79.8 59.77,79.8 60.11,80.15 60.11,81.3 59.85,81.55 52.33,81.55 51.83,82.05 51.35,82.05 51.06,81.76 51.06,81.25 52.33,79.98 52.33,78.98 50.81,77.46 50.81,68.68 48.69,66.57 23.31,66.57 22.6,65.86 22.6,61.61 22.42,61.43 22.18,61.43 21.96,61.64 21.96,65.21 21.45,65.72 21.06,65.72 20.52,65.18 20.52,61.33 22.52,59.33 22.52,57.43 20.2,55.11 20.2,50.58 22.18,48.6 22.18,46.62 20.05,44.48 20.05,42 19.93,41.88 19.64,41.88 19.53,41.99 v1(19.53,42.39)
  BOTTOM w0.108: J500.H05 v1(58.08,75.71)
S_DCLKA_P: length 124.5
  TOP w0.191: U8.C3 v1(19.53,41.12)
  05_SIG2 w0.108: v1(56.81,75.71) 56.92,75.6 57.15,75.6 57.4,75.84 57.4,76.04 57.21,76.22 52.37,76.22 52.12,76.48 52.12,77.46 52.39,77.74 59.66,77.74 59.86,77.94 59.86,78.77 59.66,78.97 53.24,78.97 52.98,79.23 52.98,79.71 53.32,80.06 59.66,80.06 59.85,80.25 59.85,81.19 59.75,81.3 52.22,81.3 51.72,81.8 51.46,81.8 51.31,81.65 51.31,81.36 52.58,80.08 52.58,78.88 51.06,77.36 51.06,68.58 48.8,66.31 23.42,66.31 22.86,65.75 22.86,61.51 22.52,61.17 22.07,61.17 21.71,61.54 21.71,65.1 21.35,65.46 21.16,65.46 20.77,65.07 20.77,61.43 22.77,59.43 22.77,57.32 20.45,55 20.45,50.68 22.43,48.7 22.43,46.51 20.3,44.38 20.3,41.9 20.03,41.63 19.64,41.63 19.53,41.52 v1(19.53,41.12)
  BOTTOM w0.108: J500.H04 v1(56.81,75.71)
S_DCLKB_N: length 149.7
  TOP w0.191: U8.Y4 v1(20.8,16.99)
  10_SIG4 w0.108: v1(20.8,16.99) 21.2,16.99 21.31,16.88 21.31,15.5 21.04,15.22 16.77,15.22 15.44,16.54 15.44,42.98 19.2,46.74 19.2,48.46 21.39,50.64 24.25,50.64 26.69,53.09 35.74,53.09 37.32,54.66 47.79,54.66 48.24,55.11 48.24,55.59 47.87,55.96 36.95,55.96 35.28,54.3 33.04,54.3 32.93,54.41 32.93,54.82 33.11,55 34.96,55 36.55,56.6 58.52,56.6 59.16,57.25 59.16,60.64 59.54,61.01 63.24,61.01 64.31,62.08 64.31,63.55 60.74,67.12 59.92,67.12 56.92,70.12 56.92,71.57 56.06,72.43 55.29,72.43 55.03,72.69 55.03,76.58 54.87,76.75 54.87,77.07 55.01,77.21 55.43,77.21 55.54,77.1 v1(55.54,76.98)
  BOTTOM w0.108: J500.G03 v1(55.54,76.98)
S_DCLKB_P: length 149.7
  TOP w0.191: U8.Y5 v1(22.07,16.99)
  10_SIG4 w0.108: v1(22.07,16.99) 21.67,16.99 21.57,16.88 21.57,15.39 21.14,14.96 16.66,14.96 15.19,16.44 15.19,43.08 18.95,46.84 18.95,48.56 21.28,50.9 24.14,50.9 26.59,53.34 35.63,53.34 37.21,54.92 47.68,54.92 47.98,55.22 47.98,55.49 47.76,55.7 37.05,55.7 35.39,54.04 32.93,54.04 32.67,54.3 32.67,54.93 33,55.26 34.85,55.26 36.45,56.85 58.41,56.85 58.91,57.35 58.91,60.74 59.43,61.26 63.14,61.26 64.05,62.18 64.05,63.44 60.63,66.86 59.81,66.86 56.67,70.01 56.67,71.46 55.95,72.18 55.19,72.18 54.78,72.59 54.78,76.47 v1(54.27,76.98)
  BOTTOM w0.108: J500.G02 v1(54.27,76.98)
S_DDA00_N: length 124.4
  TOP w0.191: U8.E10 v1(28.42,38.58)
  03_SIG1 w0.108: v1(28.42,38.58) 28.83,38.58 28.93,38.69 28.93,40.11 28.68,40.36 28.09,40.36 27.66,40.78 27.66,42.81 28.01,43.16 28.79,43.16 28.93,43.3 28.93,44.21 29.22,44.5 35.17,44.5 35.35,44.68 35.35,44.98 35.15,45.18 28.31,45.18 26.22,47.26 19.36,47.26 18.87,47.75 18.87,48.99 19.86,49.97 21.14,49.97 21.93,49.18 23.24,49.18 24.09,50.03 26.24,50.03 27.46,51.25 27.46,57.51 27.8,57.84 31.13,57.84 32.12,58.83 32.12,63.23 32.47,63.58 33,63.58 33.37,63.22 33.37,56.76 34.6,55.52 38.11,55.52 39.8,57.2 39.8,64.56 40.27,65.03 44.24,65.03 44.7,64.57 44.7,60.54 44.92,60.33 45.3,60.33 45.51,60.53 45.51,64.33 46.2,65.03 48.45,65.03 52.46,69.04 52.46,72.36 52.21,72.61 52.21,76.03 52.66,76.47 53.22,76.47 53.5,76.76 53.5,77.33 53.92,77.75 59.86,77.75 v1(60.62,76.98)
  BOTTOM w0.108: J500.G07 v1(60.62,76.98)
S_DDA00_P: length 124.4
  TOP w0.191: U8.E11 v1(29.69,38.58)
  03_SIG1 w0.108: v1(29.69,38.58) 29.5,38.38 29.31,38.38 29.19,38.5 29.19,40.21 28.79,40.61 28.19,40.61 27.92,40.89 27.92,42.71 28.11,42.9 28.89,42.9 29.19,43.2 29.19,44.11 29.32,44.25 35.27,44.25 35.6,44.58 35.6,45.09 35.26,45.43 28.41,45.43 26.33,47.52 19.46,47.52 19.13,47.85 19.13,48.88 19.97,49.72 21.03,49.72 21.83,48.92 23.35,48.92 24.2,49.77 26.34,49.77 27.72,51.15 27.72,57.4 27.91,57.59 31.24,57.59 32.38,58.73 32.38,63.13 32.57,63.32 32.9,63.32 33.11,63.11 33.11,56.65 34.5,55.26 38.22,55.26 40.05,57.1 40.05,64.45 40.38,64.77 44.14,64.77 44.45,64.46 44.45,60.44 44.81,60.07 45.41,60.07 45.76,60.42 45.76,64.23 46.3,64.77 48.56,64.77 52.72,68.93 52.72,72.46 52.47,72.71 52.47,75.92 52.76,76.22 53.32,76.22 53.76,76.65 53.76,77.22 54.03,77.49 59.75,77.49 59.97,77.27 59.97,76.97 59.86,76.86 59.47,76.86 v1(59.35,76.98)
  BOTTOM w0.108: J500.G06 v1(59.35,76.98)
S_DDA01_N: length 124.5
  TOP w0.191: U8.D6 v1(23.34,39.85)
  03_SIG1 w0.108: v1(63.16,82.06) 62.79,81.69 62.79,81.43 62.65,81.29 62.65,80.16 62.2,79.71 53.41,79.71 51.06,77.36 51.06,69.75 47.97,66.66 39.06,66.66 38.19,65.8 38.19,58.65 37.33,57.79 35.71,57.79 34.89,58.6 34.89,66.39 34.61,66.68 31.03,66.68 30.48,66.14 30.48,59.85 30.16,59.53 29.63,59.53 29.31,59.84 29.31,65.9 28.84,66.38 24.71,66.38 22.55,64.22 22.55,57.63 23.37,56.8 24.98,56.8 25.84,55.95 25.84,52.28 25.18,51.63 19.16,51.63 17.27,49.74 17.27,46.02 17.72,45.58 23.52,45.58 24.11,44.99 24.11,40.76 23.71,40.36 23.45,40.36 23.34,40.25 v1(23.34,39.85)
  BOTTOM w0.108: J500.D09 v1(63.16,82.06)
S_DDA01_P: length 124.5
  TOP w0.191: U8.C6 v1(23.34,41.12)
  03_SIG1 w0.108: v1(61.89,82.06) 61.9,82.08 62.37,82.08 62.53,81.91 62.53,81.54 62.4,81.4 62.4,80.27 62.1,79.97 53.31,79.97 50.8,77.46 50.8,69.86 47.87,66.92 38.95,66.92 37.94,65.9 37.94,58.75 37.22,58.04 35.81,58.04 35.15,58.71 35.15,66.5 34.71,66.94 30.93,66.94 30.23,66.24 30.23,59.96 30.06,59.79 29.73,59.79 29.57,59.95 29.57,66.01 28.94,66.63 24.6,66.63 22.29,64.32 22.29,57.52 23.27,56.55 24.87,56.55 25.58,55.84 25.58,52.39 25.07,51.88 19.05,51.88 17.02,49.84 17.02,45.92 17.61,45.32 23.42,45.32 23.86,44.88 23.86,40.86 23.61,40.61 23.45,40.61 23.34,40.72 v1(23.34,41.12)
  BOTTOM w0.108: J500.D08 v1(61.89,82.06)
S_DDA02_N: length 124.5
  TOP w0.191: U8.E3 v1(19.53,38.58)
  05_SIG2 w0.108: v1(19.53,38.58) 18.77,39.35 18.77,42.82 17.58,44.01 17.58,46.09 18.59,47.1 20.09,47.1 20.6,47.61 20.6,48.9 19.24,50.26 19.24,54.43 18.59,55.07 18.59,55.86 19.54,56.81 20.2,56.81 21.55,58.16 21.55,58.94 19.52,60.97 19.52,65.46 21.51,67.45 48.33,67.45 49.86,68.98 49.86,84.62 50.61,85.36 62.29,85.36 62.65,85.01 62.65,84.19 62.3,83.84 52.19,83.84 52.03,83.68 52.03,82.97 52.18,82.82 61.11,82.82 61.38,82.55 61.38,76.22 v1(61.89,75.71)
  BOTTOM w0.108: J500.H08 v1(61.89,75.71)
S_DDA02_P: length 124.5
  TOP w0.191: U8.D3 v1(19.53,39.85)
  05_SIG2 w0.108: v1(60.62,75.71) 60.8,75.53 61.13,75.53 61.28,75.69 61.28,75.96 61.13,76.12 61.13,82.45 61,82.57 52.07,82.57 51.78,82.86 51.78,83.78 52.09,84.09 62.2,84.09 62.4,84.29 62.4,84.9 62.19,85.11 50.71,85.11 50.11,84.51 50.11,68.87 48.44,67.2 21.62,67.2 19.77,65.35 19.77,61.08 21.8,59.04 21.8,58.06 20.31,56.56 19.65,56.56 18.84,55.76 18.84,55.18 19.49,54.53 19.49,50.36 20.85,49 20.85,47.51 20.19,46.85 18.7,46.85 17.84,45.99 17.84,44.11 19.02,42.93 19.02,39.45 19.28,39.2 19.49,39.2 19.66,39.38 19.66,39.72 v1(19.53,39.85)
  BOTTOM w0.108: J500.H07 v1(60.62,75.71)
S_DDA03_N: length 124.4
  TOP w0.191: U8.C7 v1(24.61,41.12)
  05_SIG2 w0.108: v1(64.43,76.98) 64.26,76.81 63.89,76.81 63.77,76.93 63.77,77.24 64.02,77.49 65.99,77.49 66.2,77.28 66.2,71.03 65.46,70.29 56.26,70.29 53.48,67.52 53.48,66.42 52.02,64.96 50.93,64.96 44.04,58.08 39.88,58.08 39.7,58.26 39.7,58.48 39.93,58.72 43.81,58.72 44.09,59 44.09,59.63 43.83,59.89 39.49,59.89 36.83,57.23 36.83,56.92 35.76,55.84 32.6,55.84 31.4,54.64 30.98,54.64 30.62,54.99 29.7,54.99 29.49,54.78 28.72,54.78 28.51,54.99 28.51,55.57 28.22,55.85 27.58,55.85 27.32,55.59 27.32,53.97 28.14,53.15 29.53,53.15 29.81,52.86 29.81,52.16 29.36,51.7 29.36,49.6 29.14,49.38 28.76,49.38 28.52,49.62 28.52,50.24 26.55,52.22 26.55,55.72 27.29,56.47 35.51,56.47 35.87,56.82 35.87,57.4 35.61,57.66 26.81,57.66 25.05,55.91 25.05,51.95 26.47,50.53 26.47,46.25 25.12,44.9 25.12,41.34 24.91,41.12 v1(24.61,41.12)
  BOTTOM w0.108: J500.G10 v1(64.43,76.98)
S_DDA03_P: length 124.4
  TOP w0.191: U8.C8 v1(25.88,41.12)
  05_SIG2 w0.108: v1(63.16,76.98) 63.92,77.74 66.1,77.74 66.46,77.38 66.46,70.93 65.57,70.04 56.36,70.04 53.74,67.41 53.74,66.32 52.12,64.71 51.03,64.71 44.15,57.83 39.78,57.83 39.44,58.16 39.44,58.59 39.83,58.97 43.71,58.97 43.84,59.1 43.84,59.53 43.73,59.64 39.59,59.64 37.09,57.13 37.09,56.81 35.86,55.59 32.71,55.59 31.51,54.38 30.87,54.38 30.52,54.74 29.81,54.74 29.59,54.52 28.61,54.52 28.25,54.88 28.25,55.46 28.12,55.6 27.69,55.6 27.57,55.48 27.57,54.08 28.25,53.4 29.63,53.4 30.07,52.97 30.07,52.05 29.61,51.6 29.61,49.5 29.24,49.13 28.65,49.13 28.27,49.51 28.27,50.14 26.29,52.12 26.29,55.83 27.19,56.72 35.41,56.72 35.62,56.93 35.62,57.3 35.51,57.41 26.91,57.41 25.31,55.8 25.31,52.06 26.73,50.64 26.73,46.15 25.38,44.8 25.38,41.63 v1(25.88,41.12)
  BOTTOM w0.108: J500.G09 v1(63.16,76.98)
S_DDA04_N: length 124.5
  TOP w0.191: U8.D8 v1(25.88,39.85)
  05_SIG2 w0.108: v1(25.88,39.85) 25.48,39.85 25.38,39.96 25.38,40.27 25.05,40.6 24.31,40.6 24.11,40.8 24.11,45.34 25.18,46.41 25.18,50.22 24.43,50.97 24.43,56.4 25.02,56.99 25.02,57.61 29.96,62.55 42.9,62.55 43.12,62.33 43.12,62.03 42.94,61.85 30.17,61.85 29.61,61.29 29.61,60.69 30.08,60.23 36.55,60.23 36.77,60.01 36.77,59.67 36.58,59.48 27.78,59.48 27.44,59.13 27.44,58.65 27.78,58.3 37.03,58.3 37.98,59.26 37.98,60.26 38.44,60.72 45.7,60.72 53.76,68.79 53.76,73.4 54.05,73.68 64.79,73.68 65.19,74.08 65.19,75.6 65.3,75.71 v1(65.7,75.71)
  BOTTOM w0.108: J500.H11 v1(65.7,75.71)
S_DDA04_P: length 124.5
  TOP w0.191: U8.D7 v1(24.61,39.85)
  05_SIG2 w0.108: v1(24.61,39.85) 25.01,39.85 25.12,39.96 25.12,40.17 24.95,40.34 24.21,40.34 23.85,40.7 23.85,45.45 24.92,46.52 24.92,50.12 24.18,50.87 24.18,56.51 24.76,57.1 24.76,57.71 29.85,62.8 43.01,62.8 43.38,62.43 43.38,61.93 43.04,61.59 30.27,61.59 29.87,61.19 29.87,60.8 30.19,60.48 36.65,60.48 37.02,60.11 37.02,59.56 36.68,59.22 27.89,59.22 27.69,59.03 27.69,58.75 27.89,58.55 36.92,58.55 37.73,59.36 37.73,60.37 38.34,60.98 45.59,60.98 53.51,68.89 53.51,73.5 53.94,73.93 64.69,73.93 64.94,74.18 64.94,75.6 64.83,75.71 v1(64.43,75.71)
  BOTTOM w0.108: J500.H10 v1(64.43,75.71)
S_DDA05_N: length 124.5
  TOP w0.191: U8.E6 v1(23.34,38.58)
  05_SIG2 w0.108: v1(23.34,38.58) 22.58,37.82 15.82,37.82 14.73,38.91 14.73,43.99 15.03,44.29 15.73,44.29 15.98,44.03 15.98,39.58 16.22,39.34 17.35,39.34 17.5,39.5 17.5,41.52 16.69,42.34 16.69,48.42 17.06,48.79 17.37,48.79 17.62,49.03 17.62,49.39 17.37,49.64 16.51,49.64 16.11,50.04 16.11,52.21 17.11,53.2 17.11,55.87 18.53,57.3 18.53,66.22 20.65,68.33 47.96,68.33 48.96,69.33 48.96,85.97 49.87,86.88 63.63,86.88 63.92,86.59 63.92,82.96 64.06,82.82 66.21,82.82 v1(66.97,82.06)
  BOTTOM w0.108: J500.D12 v1(66.97,82.06)
S_DDA05_P: length 124.5
  TOP w0.191: U8.E5 v1(22.07,38.58)
  05_SIG2 w0.108: v1(22.07,38.58) 22.24,38.75 22.6,38.75 22.73,38.62 22.73,38.33 22.48,38.07 15.93,38.07 14.98,39.02 14.98,43.89 15.13,44.04 15.62,44.04 15.73,43.93 15.73,39.47 16.11,39.09 17.46,39.09 17.76,39.39 17.76,41.63 16.94,42.44 16.94,48.31 17.17,48.53 17.48,48.53 17.87,48.93 17.87,49.5 17.47,49.89 16.62,49.89 16.37,50.14 16.37,52.1 17.36,53.1 17.36,55.77 18.79,57.19 18.79,66.11 20.76,68.08 48.07,68.08 49.21,69.22 49.21,85.86 49.97,86.63 63.53,86.63 63.67,86.48 63.67,82.86 63.96,82.57 66.11,82.57 66.36,82.32 66.36,81.87 66.19,81.7 65.88,81.7 65.7,81.88 v1(65.7,82.06)
  BOTTOM w0.108: J500.D11 v1(65.7,82.06)
S_DDA06_N: length 124.5
  TOP w0.191: U8.C5 v1(22.07,41.12)
  03_SIG1 w0.108: v1(22.07,41.12) 21.67,41.12 21.57,41.01 21.57,40.86 21.82,40.61 22.35,40.61 22.58,40.84 22.58,44.1 22.26,44.43 16.9,44.43 16.09,45.23 16.09,51.7 17.15,52.76 24.21,52.76 24.69,53.24 24.69,55.27 24.38,55.58 22.83,55.58 21.37,57.04 21.37,64.83 24.36,67.82 35.5,67.82 36.07,67.25 36.07,59.22 36.25,59.03 36.69,59.03 36.93,59.27 36.93,66.96 37.82,67.85 47.55,67.85 49.58,69.88 49.58,83.77 52.49,86.69 64.75,86.69 65.19,86.25 65.19,83.44 65.3,83.33 v1(65.7,83.33)
  BOTTOM w0.108: J500.C11 v1(65.7,83.33)
S_DDA06_P: length 124.5
  TOP w0.191: U8.C4 v1(20.8,41.12)
  03_SIG1 w0.108: v1(20.8,41.12) 21.2,41.12 21.31,41.01 21.31,40.76 21.71,40.36 22.46,40.36 22.83,40.73 22.83,44.21 22.36,44.68 17.01,44.68 16.35,45.34 16.35,51.6 17.25,52.5 24.31,52.5 24.95,53.14 24.95,55.38 24.49,55.84 22.93,55.84 21.63,57.14 21.63,64.72 24.47,67.56 35.4,67.56 35.82,67.14 35.82,59.11 36.15,58.78 36.79,58.78 37.18,59.17 37.18,66.86 37.92,67.6 47.65,67.6 49.83,69.78 49.83,83.67 52.6,86.43 64.65,86.43 64.94,86.14 64.94,83.44 64.83,83.33 v1(64.43,83.33)
  BOTTOM w0.108: J500.C10 v1(64.43,83.33)
S_DDA07_N: length 124.5
  TOP w0.191: U8.B8 v1(25.88,42.39)
  05_SIG2 w0.108: v1(25.88,42.39) 26.39,42.9 26.39,44.87 28.8,47.28 30.62,47.28 30.97,46.93 30.97,46.31 30.54,45.89 29.13,45.89 27.91,44.67 27.91,40.74 28.03,40.62 31.68,40.62 31.83,40.77 31.83,41.46 31.66,41.63 29.24,41.63 28.93,41.93 28.93,44.66 29.43,45.15 31.14,45.15 31.68,45.69 31.68,48.56 30.7,49.54 30.7,52.68 32.66,54.65 33.25,54.65 33.53,54.37 33.53,53.9 32.13,52.5 32.13,51.99 32.99,51.13 32.99,47.29 33.2,47.07 33.42,47.07 33.62,47.27 33.62,52.3 38.53,57.21 44.49,57.21 51.01,63.73 52.06,63.73 54.45,66.13 54.45,67.18 56.63,69.35 64.18,69.35 64.55,68.99 64.55,68.43 64.19,68.07 57.25,68.07 57.05,67.87 57.05,67.61 57.25,67.41 64.44,67.41 67.47,70.45 67.47,76.1 67.85,76.48 68.75,76.48 v1(69.51,75.71)
  BOTTOM w0.108: J500.H14 v1(69.51,75.71)
S_DDA07_P: length 124.5
  TOP w0.191: U8.B9 v1(27.15,42.39)
  05_SIG2 w0.108: v1(68.24,75.71) 68.36,75.59 68.68,75.59 68.78,75.7 68.78,76.08 68.64,76.22 67.96,76.22 67.73,75.99 67.73,70.34 64.54,67.15 57.14,67.15 56.79,67.5 56.79,67.98 57.14,68.32 64.08,68.32 64.3,68.54 64.3,68.88 64.08,69.1 56.74,69.1 54.71,67.07 54.71,66.02 52.17,63.48 51.12,63.48 44.59,56.95 38.63,56.95 33.87,52.19 33.87,47.16 33.53,46.81 33.1,46.81 32.73,47.18 32.73,51.02 31.87,51.88 31.87,52.6 33.28,54.01 33.28,54.26 33.15,54.39 32.77,54.39 30.95,52.58 30.95,49.65 31.94,48.66 31.94,45.59 31.25,44.9 29.53,44.9 29.19,44.55 29.19,42.04 29.34,41.88 31.77,41.88 32.09,41.57 32.09,40.66 31.79,40.36 27.93,40.36 27.66,40.63 27.66,44.77 29.03,46.14 30.44,46.14 30.71,46.41 30.71,46.83 30.51,47.03 28.91,47.03 26.65,44.77 26.65,42.4 26.75,42.29 27.05,42.29 v1(27.15,42.39)
  BOTTOM w0.108: J500.H13 v1(68.24,75.71)
S_DDA08_N: length 124.4
  TOP w0.191: U8.B6 v1(23.34,42.39)
  05_SIG2 w0.108: v1(68.24,76.98) 67.88,77.34 67.88,77.68 67.73,77.83 67.73,78.65 67.36,79.02 62.8,79.02 62.4,78.62 62.4,75.5 62.1,75.2 52.63,75.2 52.17,74.74 52.17,68.8 49.07,65.69 47.29,65.69 45.38,63.78 28.76,63.78 28.65,63.89 28.65,64.27 28.79,64.41 44.15,64.41 44.56,64.82 44.56,65.19 44.06,65.69 24.77,65.69 24.5,65.43 24.5,64.8 24.76,64.55 26.48,64.55 27.35,63.67 27.35,61.55 23.61,57.81 23.61,57.27 21.1,54.76 21.1,52.31 22.73,50.69 23.06,50.69 23.28,50.46 23.28,46.43 21.32,44.47 21.32,42.02 21.7,41.64 22.59,41.64 v1(23.34,42.39)
  BOTTOM w0.108: J500.G13 v1(68.24,76.98)
S_DDA08_P: length 124.4
  TOP w0.191: U8.B5 v1(22.07,42.39)
  05_SIG2 w0.108: v1(66.97,76.98) 67.25,76.71 67.5,76.71 67.63,76.83 67.63,77.58 67.48,77.73 67.48,78.55 67.26,78.77 62.91,78.77 62.65,78.51 62.65,75.4 62.21,74.95 52.74,74.95 52.43,74.64 52.43,68.7 49.17,65.44 47.4,65.44 45.49,63.53 28.65,63.53 28.39,63.79 28.39,64.38 28.68,64.67 44.05,64.67 44.31,64.93 44.31,65.08 43.95,65.44 24.87,65.44 24.75,65.32 24.75,64.91 24.86,64.8 26.58,64.8 27.61,63.77 27.61,61.45 23.87,57.71 23.87,57.16 21.36,54.65 21.36,52.42 22.83,50.95 23.16,50.95 23.54,50.57 23.54,46.33 21.57,44.36 21.57,42.12 21.8,41.89 22.48,41.89 22.75,42.15 22.75,42.48 22.58,42.65 22.21,42.65 22.07,42.51 v1(22.07,42.39)
  BOTTOM w0.108: J500.G12 v1(66.97,76.98)
S_DDA09_N: length 124.4
  TOP w0.191: U8.C10 v1(28.42,41.12)
  03_SIG1 w0.108: v1(70.78,82.06) 70.27,81.55 70.27,79.92 70.49,79.7 72.25,79.7 72.81,79.13 72.81,76.67 72.36,76.22 55.33,76.22 53.76,74.65 53.76,72.85 54.06,72.55 54.06,69 48.9,63.84 48.34,63.84 46.67,62.17 46.67,60.07 45.73,59.13 44.42,59.13 43.46,60.09 43.46,63.34 43.01,63.78 41.29,63.78 40.98,63.47 40.98,55.55 41.62,54.91 41.62,51.31 40.3,50 36.05,50 35.76,50.29 35.76,50.84 36.14,51.22 39.09,51.22 39.59,51.73 39.59,53.96 39.19,54.36 34.16,54.36 31.94,56.58 30.25,56.58 29.33,55.66 29.33,53.54 30.03,52.85 30.03,50.57 28.48,49.02 28.48,46.9 29.08,46.3 35.87,46.3 36.48,45.69 36.48,44.2 35.53,43.25 34.49,43.25 32.88,41.63 28.53,41.63 28.42,41.52 v1(28.42,41.12)
  BOTTOM w0.108: J500.D15 v1(70.78,82.06)
S_DDA09_P: length 124.4
  TOP w0.191: U8.B10 v1(28.42,42.39)
  03_SIG1 w0.108: v1(69.51,82.06) 70.04,82.06 70.14,81.95 70.14,81.79 70.02,81.66 70.02,79.81 70.38,79.45 72.14,79.45 72.56,79.03 72.56,76.77 72.26,76.47 55.23,76.47 53.51,74.76 53.51,72.74 53.81,72.45 53.81,69.1 48.8,64.09 48.24,64.09 46.42,62.28 46.42,60.18 45.62,59.38 44.53,59.38 43.71,60.2 43.71,63.45 43.12,64.04 41.18,64.04 40.72,63.58 40.72,55.45 41.36,54.81 41.36,51.41 40.2,50.25 36.15,50.25 36.01,50.39 36.01,50.73 36.25,50.97 39.19,50.97 39.85,51.62 39.85,54.06 39.3,54.62 34.26,54.62 32.05,56.83 30.15,56.83 29.08,55.76 29.08,53.44 29.77,52.75 29.77,50.67 28.22,49.12 28.22,46.8 28.97,46.05 35.77,46.05 36.23,45.59 36.23,44.31 35.42,43.5 34.39,43.5 32.77,41.88 28.53,41.88 28.42,41.99 v1(28.42,42.39)
  BOTTOM w0.108: J500.D14 v1(69.51,82.06)
S_DDA10_N: length 124.5
  TOP w0.191: U8.A9 v1(27.15,43.66)
  03_SIG1 w0.108: v1(70.78,83.33) 70.03,84.08 69.03,84.08 68.74,83.8 68.74,80.58 67.19,79.03 53.69,79.03 51.57,76.91 51.57,69.38 48.2,66.01 39.6,66.01 38.88,65.29 38.88,57.69 37.64,56.45 35.37,56.45 34.25,57.57 34.25,65.68 33.89,66.04 31.61,66.04 31.14,65.57 31.14,59.38 30.52,58.77 29.08,58.77 28.65,59.2 28.65,64.12 28.32,64.44 27.77,64.44 27.46,64.13 27.46,59.6 26.56,58.7 26.56,52.09 25.43,50.97 19.58,50.97 17.93,49.31 17.93,47.28 18.95,46.26 25.58,46.26 27.65,44.19 27.65,43.77 27.54,43.66 v1(27.15,43.66)
  BOTTOM w0.108: J500.C15 v1(70.78,83.33)
S_DDA10_P: length 124.5
  TOP w0.191: U8.A10 v1(28.42,43.66)
  03_SIG1 w0.108: v1(28.42,43.66) 28.06,43.66 27.9,43.82 27.9,44.3 25.69,46.51 19.06,46.51 18.18,47.39 18.18,49.2 19.69,50.71 25.54,50.71 26.81,51.98 26.81,58.59 27.72,59.5 27.72,64.03 27.88,64.19 28.22,64.19 28.39,64.01 28.39,59.1 28.98,58.52 30.63,58.52 31.39,59.28 31.39,65.46 31.72,65.79 33.79,65.79 34,65.57 34,57.46 35.27,56.19 37.74,56.19 39.13,57.58 39.13,65.19 39.7,65.76 48.3,65.76 51.83,69.28 51.83,76.8 53.8,78.77 67.3,78.77 69,80.47 69,83.7 69.13,83.83 69.92,83.83 70.22,83.53 70.22,83.29 70,83.06 69.78,83.06 v1(69.51,83.33)
  BOTTOM w0.108: J500.C14 v1(69.51,83.33)
S_DDA11_N: length 124.5
  TOP w0.191: U8.C13 v1(33.5,41.12)
  05_SIG2 w0.108: v1(33.5,41.12) 33.85,41.12 34.01,41.29 34.01,44.92 36.24,47.15 36.24,49.88 37.76,51.4 37.76,53.72 39.48,55.44 45.45,55.44 50.99,60.98 52.02,60.98 54.24,63.19 62.84,63.19 68.39,68.74 69.9,68.74 73.83,72.67 73.83,84.91 74.28,85.37 92.74,85.37 92.87,85.5 92.87,86.4 92.67,86.6 73.04,86.6 72.81,86.37 72.81,75.56 72.92,75.46 73.14,75.46 73.32,75.63 v1(73.32,75.71)
  BOTTOM w0.108: J500.H17 v1(73.32,75.71)
S_DDA11_P: length 124.5
  TOP w0.191: U8.C14 v1(34.77,41.12)
  05_SIG2 w0.108: v1(72.05,75.71) 72.56,76.22 72.56,86.48 72.94,86.86 92.77,86.86 93.13,86.5 93.13,85.39 92.85,85.11 74.38,85.11 74.08,84.81 74.08,72.57 70,68.49 68.5,68.49 62.95,62.94 54.35,62.94 52.13,60.72 51.09,60.72 45.55,55.18 39.58,55.18 38.01,53.61 38.01,51.29 36.5,49.78 36.5,47.05 34.27,44.82 34.27,41.63 v1(34.77,41.12)
  BOTTOM w0.108: J500.H16 v1(72.05,75.71)
S_DDA12_N: length 124.4
  TOP w0.191: U8.B12 v1(30.96,42.39)
  05_SIG2 w0.108: v1(30.96,42.39) 31.17,42.39 31.47,42.7 31.47,43.96 31.81,44.29 32.26,44.29 32.61,43.94 32.61,43.36 32.75,43.22 33.01,43.22 33.13,43.34 33.13,45.47 35.14,47.48 35.14,50.6 35.94,51.4 35.94,53.3 38.94,56.31 44.9,56.31 51,62.41 52.07,62.41 54.9,65.23 55.99,65.23 56.91,66.16 61.79,66.16 62.05,65.9 62.05,65.28 61.79,65.02 58.3,65.02 58.16,64.88 58.16,64.52 58.28,64.41 62.76,64.41 68.05,69.7 69.64,69.7 70.01,70.07 70.01,78.83 69.48,79.37 62.77,79.37 62.4,79.75 62.4,81.17 62.79,81.56 64.79,81.56 65.19,81.15 65.19,80.47 65.39,80.28 67.37,80.28 67.48,80.38 67.48,83.73 67.37,83.84 65.26,83.84 64.94,84.16 64.94,86.4 65.26,86.72 68.53,86.72 69,86.25 69,81.83 69.28,81.55 69.9,81.55 70.02,81.67 70.02,85.09 70.3,85.37 71.26,85.37 71.54,85.08 71.54,77.49 v1(72.05,76.98)
  BOTTOM w0.108: J500.G16 v1(72.05,76.98)
S_DDA12_P: length 124.4
  TOP w0.191: U8.B13 v1(32.23,42.39)
  05_SIG2 w0.108: v1(70.78,76.98) 70.78,76.81 70.89,76.7 71.17,76.7 71.28,76.82 71.28,84.98 71.15,85.11 70.4,85.11 70.27,84.98 70.27,81.57 70,81.3 69.17,81.3 68.75,81.72 68.75,86.15 68.43,86.46 65.36,86.46 65.19,86.29 65.19,84.27 65.37,84.09 67.48,84.09 67.73,83.84 67.73,80.28 67.48,80.02 65.29,80.02 64.94,80.37 64.94,81.05 64.68,81.3 62.89,81.3 62.65,81.06 62.65,79.85 62.88,79.62 69.58,79.62 70.27,78.94 70.27,69.97 69.75,69.45 68.16,69.45 62.86,64.15 58.17,64.15 57.91,64.41 57.91,64.99 58.19,65.27 61.69,65.27 61.79,65.38 61.79,65.79 61.69,65.9 57.02,65.9 56.1,64.98 55.01,64.98 52.18,62.15 51.1,62.15 45,56.05 39.05,56.05 36.19,53.2 36.19,51.29 35.39,50.49 35.39,47.37 33.39,45.36 33.39,43.23 33.12,42.96 32.65,42.96 32.36,43.25 32.36,43.84 32.16,44.04 31.91,44.04 31.73,43.85 31.73,42.5 31.83,42.39 v1(32.23,42.39)
  BOTTOM w0.108: J500.G15 v1(70.78,76.98)
S_DDA13_N: length 124.5
  TOP w0.191: U8.C17 v1(38.58,41.12)
  03_SIG1 w0.108: v1(38.58,41.12) 38.18,41.12 38.08,41.23 38.08,45.9 36.71,47.26 30.38,47.26 30.23,47.41 30.23,49.11 30.96,49.84 30.96,53.99 31.55,54.58 32.58,54.58 33.69,53.46 38.61,53.46 38.72,53.35 38.72,52.93 38.61,52.82 34.26,52.82 32.79,51.35 32.79,49.06 33.1,48.75 34.71,48.75 35.02,49.07 41.9,49.07 43.2,50.36 43.2,54.62 41.88,55.93 41.88,62.6 42,62.72 42.44,62.72 42.56,62.6 42.56,58.04 43.51,57.1 47,57.1 47.76,57.86 47.76,61.81 48.64,62.68 50.27,62.68 53.38,65.79 53.38,67.08 55.03,68.74 55.03,74.72 55.27,74.95 74.94,74.95 75.35,75.36 75.35,80.16 74.08,81.43 74.08,81.95 74.19,82.06 v1(74.59,82.06)
  BOTTOM w0.108: J500.D18 v1(74.59,82.06)
